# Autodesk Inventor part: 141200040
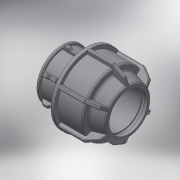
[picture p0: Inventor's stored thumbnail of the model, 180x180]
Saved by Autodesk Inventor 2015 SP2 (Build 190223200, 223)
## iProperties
Created: 2017-08
Part Number: 141200040
Material: Generic
Description: PLASSON L.14 END PLUG (SILVER) 40
Document SubType Name: Modeling
Designer: KIM
Density: 1 g/cm^3
Appearance: Default
Author: KIM
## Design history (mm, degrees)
derived "141200.ipt"
feature "Solid1::141200.ipt"
tag "TaggingFeature1"
body "Solid1"
other parameters: "d4" = 15 deg, "d5" = 44.22, "d6" = 14.5926, "d10" = 73, "d16" = 40.8, "d17" = 3.35, "d22" = 48, "d24" = 3.35, "d25" = 65.7, "d26" = 54.75, "d27" = 3.35, "d28" = 135 deg, "d29" = 2.01, "d31" = 2, "d44" = 0.8, "d46" = 150 deg, "d49" = 3.65, "d50" = 0, "d51" = 2.19, "d52" = 1.46, "d53" = 45 deg, "d54" = 16, "d55" = 6.4, "d56" = 3.65, "d57" = 0, "d58" = 1.2, "d59" = 0.8, "d61" = 360 deg, "d66" = 52, "d68" = 67, "d69" = 2.4, "E_" = 73, "l_" = 67
